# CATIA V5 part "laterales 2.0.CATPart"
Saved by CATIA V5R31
Part number: laterales 2.0
Bounding box of the stored display mesh (mm): x 0 to 3.3, y -96.6 to 96.6, z 0 to 315
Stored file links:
  C:\Users\189361\Desktop\laterales 2.0.CATPart
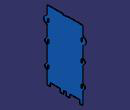
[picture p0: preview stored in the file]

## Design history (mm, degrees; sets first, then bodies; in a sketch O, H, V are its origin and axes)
Body1 (main body)
  Sketch1 on yz-plane, origin (0, 0, 0), H (0, 1, 0), V (0, 0, 1)
    point P1 (0, 15)
    line L1 (0, 15) -> (-6.45, 15)
    point P2 (-6.45, 15)
    line L2 (-6.45, 15) -> (-6.45, 0)
    point P3 (-6.45, 0)
    line L3 (-6.45, 0) -> (-21.75, 0)
    point P4 (-21.75, 0)
    line L4 (-21.75, 0) -> (-21.75, 15)
    point P5 (-21.75, 15)
    line L5 (-21.75, 15) -> (-66.45, 15)
    point P6 (-66.45, 15)
    line L6 (-66.45, 15) -> (-66.45, 0)
    point P7 (-66.45, 0)
    line L7 (-66.45, 0) -> (-81.6, 0)
    point P8 (-81.6, 0)
    construction line L8 (-14.1, -19.5641) -> (-14.1, 21.2481)
    point P9 (-14.1, -19.5641)
    point P10 (-14.1, 21.2481)
    construction line L9 (-264.7975, 72.5) -> (-53.2108, 72.5)
    point P11 (-264.7975, 72.5)
    point P12 (-53.2108, 72.5)
    point P13 (-81.6, 80.15)
    point P14 (-75, 80.15)
    point P15 (-75, 64.85)
    point P16 (-81.6, 64.85)
    line L10 (-81.6, 89.8205) -> (-81.6, 155.1795)
    construction line L11 (-287.0733, 122.5) -> (-61.3587, 122.5)
    point P18 (-61.3587, 122.5)
    point P19 (-264.7975, 172.5)
    point P20 (-53.2108, 172.5)
    point P21 (-81.6, 164.85)
    point P22 (-75, 164.85)
    point P23 (-75, 180.15)
    point P24 (-81.6, 180.15)
    construction line L12 (-264.7975, 172.5) -> (-53.2108, 172.5)
    line L13 (-81.6, 189.8205) -> (-81.6, 232.0871)
    point P25 (-81.6, 262.65)
    line L14 (-81.6, 277.9129) -> (-81.6, 315)
    point P26 (-81.6, 315)
    line L15 (-81.6, 315) -> (-7.5, 315)
    point P27 (-7.5, 315)
    construction line L16 (-258.7443, 255) -> (-43.5524, 255)
    point P29 (-43.5524, 255)
    arc A1 centre (-81.6, 72.5) radius 10 from (-86.6, 81.1603) to (-86.6, 63.8397) ccw
    point P30 (-81.6, 72.5)
    point P31 (-80.687, 62.5418)
    point P32 (-81.6, 92.4667)
    point P33 (-81.6, 172.5)
    arc A2 centre (-81.6, 172.5) radius 10 from (-86.6, 163.8397) to (-86.6, 181.1603) cw
    arc A3 centre (-81.6, 255) radius 15 from (-87.6, 268.7477) to (-87.6, 241.2523) ccw
    point P34 (-81.6, 255)
    arc A4 centre (-91.6, 55.1795) radius 10 from (-86.6, 63.8397) to (-81.6, 55.1795) cw
    point P35 (-86.6, 63.8397)
    point P36 (-81.6, 55.1795)
    point P38 (-81.6, 89.8205)
    point P39 (-86.6, 81.1603)
    arc A5 centre (-91.6, 89.8205) radius 10 from (-86.6, 81.1603) to (-81.6, 89.8205) ccw
    point P41 (-81.6, 189.8205)
    point P42 (-86.6, 181.1603)
    arc A6 centre (-91.6, 189.8205) radius 10 from (-86.6, 181.1603) to (-81.6, 189.8205) ccw
    point P44 (-81.6, 155.1795)
    point P45 (-86.6, 163.8397)
    arc A7 centre (-91.6, 155.1795) radius 10 from (-86.6, 163.8397) to (-81.6, 155.1795) cw
    arc A8 centre (-91.6, 232.0871) radius 10 from (-87.6, 241.2523) to (-81.6, 232.0871) cw
    point P47 (-87.6, 241.2523)
    point P48 (-81.6, 232.0871)
    point P50 (-81.6, 277.9129)
    point P51 (-87.6, 268.7477)
    arc A9 centre (-91.6, 277.9129) radius 10 from (-87.6, 268.7477) to (-81.6, 277.9129) ccw
    line L17 (-7.5, 315) -> (-7.5, 311.7)
    point P53 (-7.5, 311.7)
    line L18 (-7.5, 311.7) -> (0, 311.7)
    point P54 (0, 311.7)
    point P55 (0, 0)
    construction line L19 (0, 15) -> (-81.6, 15)
    point P56 (-81.6, 15)
    line L20 (-81.6, 0) -> (-81.6, 55.1795)
    point P57 (0, 0)
    point P58 (0, 15)
    point P59 (6.45, 15)
    point P60 (6.45, 0)
    point P61 (21.75, 0)
    point P62 (21.75, 15)
    point P63 (66.45, 15)
    point P64 (66.45, 0)
    point P65 (81.6, 0)
    point P66 (14.1, 21.2481)
    point P67 (14.1, -19.5641)
    construction line L21 (14.1, -19.5641) -> (14.1, 21.2481)
    point P68 (53.2108, 72.5)
    point P69 (61.3587, 122.5)
    point P70 (53.2108, 172.5)
    point P71 (81.6, 315)
    point P72 (7.5, 315)
    point P73 (43.5524, 255)
    point P74 (80.687, 62.5418)
    point P75 (81.6, 92.4667)
    point P76 (86.6, 63.8397)
    point P77 (81.6, 55.1795)
    point P79 (81.6, 89.8205)
    point P80 (86.6, 81.1603)
    point P82 (81.6, 189.8205)
    point P83 (86.6, 181.1603)
    point P85 (81.6, 155.1795)
    point P86 (86.6, 163.8397)
    point P88 (87.6, 241.2523)
    point P89 (81.6, 232.0871)
    point P91 (81.6, 277.9129)
    point P92 (87.6, 268.7477)
    point P94 (7.5, 311.7)
    point P95 (0, 311.7)
    point P96 (0, 0)
    point P97 (81.6, 15)
    construction line L22 (0, 15) -> (81.6, 15)
    line L23 (0, 15) -> (6.45, 15)
    line L24 (6.45, 15) -> (6.45, 0)
    line L25 (6.45, 0) -> (21.75, 0)
    line L26 (21.75, 0) -> (21.75, 15)
    line L27 (21.75, 15) -> (66.45, 15)
    line L28 (66.45, 15) -> (66.45, 0)
    line L29 (66.45, 0) -> (81.6, 0)
    line L30 (81.6, 89.8205) -> (81.6, 155.1795)
    line L31 (81.6, 189.8205) -> (81.6, 232.0871)
    line L32 (81.6, 277.9129) -> (81.6, 315)
    line L33 (81.6, 315) -> (7.5, 315)
    arc A10 centre (81.6, 72.5) radius 10 from (86.6, 81.1603) to (86.6, 63.8397) cw
    arc A11 centre (81.6, 172.5) radius 10 from (86.6, 163.8397) to (86.6, 181.1603) ccw
    arc A12 centre (81.6, 255) radius 15 from (87.6, 268.7477) to (87.6, 241.2523) cw
    arc A13 centre (91.6, 55.1795) radius 10 from (86.6, 63.8397) to (81.6, 55.1795) ccw
    arc A14 centre (91.6, 89.8205) radius 10 from (86.6, 81.1603) to (81.6, 89.8205) cw
    arc A15 centre (91.6, 189.8205) radius 10 from (86.6, 181.1603) to (81.6, 189.8205) cw
    arc A16 centre (91.6, 155.1795) radius 10 from (86.6, 163.8397) to (81.6, 155.1795) ccw
    arc A17 centre (91.6, 232.0871) radius 10 from (87.6, 241.2523) to (81.6, 232.0871) ccw
    arc A18 centre (91.6, 277.9129) radius 10 from (87.6, 268.7477) to (81.6, 277.9129) cw
    line L34 (7.5, 315) -> (7.5, 311.7)
    line L35 (7.5, 311.7) -> (0, 311.7)
    line L36 (81.6, 0) -> (81.6, 55.1795)
    axis line L37 (-81.6, 72.5) -> (-75, 72.5)
    point P98 (-75, 72.5)
    point P99 (-78.3, 80.15)
    line L38 (-78.3, 80.15) -> (-75, 80.15)
    line L39 (-75, 80.15) -> (-75, 64.85)
    line L40 (-75, 64.85) -> (-78.3, 64.85)
    line L41 (-78.3, 64.85) -> (-78.3, 80.15)
    point P100 (-75, 80.15)
    point P101 (-75, 64.85)
    point P102 (-78.3, 64.85)
    point P103 (-75, 164.85)
    point P104 (-75, 180.15)
    point P105 (-75, 172.5)
    point P106 (-78.3, 164.85)
    point P107 (-75, 164.85)
    point P108 (-75, 180.15)
    point P109 (-78.3, 180.15)
    line L42 (-78.3, 164.85) -> (-75, 164.85)
    line L43 (-75, 164.85) -> (-75, 180.15)
    line L44 (-75, 180.15) -> (-78.3, 180.15)
    line L45 (-78.3, 180.15) -> (-78.3, 164.85)
    point P110 (-78.3, 262.65)
    line L46 (-78.3, 262.65) -> (-75, 262.65)
    line L47 (-75, 262.65) -> (-75, 247.35)
    line L48 (-75, 247.35) -> (-78.3, 247.35)
    line L49 (-78.3, 247.35) -> (-78.3, 262.65)
    point P111 (-75, 262.65)
    point P112 (-75, 247.35)
    point P113 (-78.3, 247.35)
    point P114 (78.3, 262.65)
    point P115 (75, 262.65)
    point P116 (75, 247.35)
    point P117 (78.3, 247.35)
    line L50 (78.3, 262.65) -> (75, 262.65)
    line L51 (75, 262.65) -> (75, 247.35)
    line L52 (75, 247.35) -> (78.3, 247.35)
    line L53 (78.3, 247.35) -> (78.3, 262.65)
    point P118 (75, 164.85)
    point P119 (75, 180.15)
    point P120 (75, 164.85)
    point P121 (75, 180.15)
    point P122 (75, 172.5)
    point P123 (78.3, 164.85)
    point P124 (75, 164.85)
    point P125 (75, 180.15)
    point P126 (78.3, 180.15)
    line L54 (78.3, 164.85) -> (75, 164.85)
    line L55 (75, 164.85) -> (75, 180.15)
    line L56 (75, 180.15) -> (78.3, 180.15)
    line L57 (78.3, 180.15) -> (78.3, 164.85)
    point P127 (75, 80.15)
    point P128 (75, 64.85)
    point P129 (75, 72.5)
    point P130 (78.3, 80.15)
    point P131 (75, 80.15)
    point P132 (75, 64.85)
    point P133 (78.3, 64.85)
    line L58 (78.3, 80.15) -> (75, 80.15)
    line L59 (75, 80.15) -> (75, 64.85)
    line L60 (75, 64.85) -> (78.3, 64.85)
    line L61 (78.3, 64.85) -> (78.3, 80.15)
    length L3 = 15.3
    distance L8 L2 = 7.65
    distance L8 V = 14.1
    length L6 = 15
    length L7 = 15.15
    distance L9 L5 = 57.5
    distance L11 L9 = 50
    distance L16 L15 = 60
    distance L15 L5 = 300
    radius A1 = 10
    radius A3 = 15
    radius A4 = 10
    radius A8 = 10
    length L18 = 7.5
    length L17 = 3.3
    length L19 = 81.6
    length L37 = 6.6
    length L38 = 3.3
    length L39 = 15.3
    distance L9 L38 = 7.65
    length L46 = 3.3
    length L47 = 15.3
    distance L46 L16 = 7.65
    coincidence: P1 V, P3 H, P5 L1, P7 H, P25 L10, P30 L9, L10 P32, P34 L10, P34 L16, L14 L13, A1 P31, P54 V, L10 P56, P33 L13, P98 L39, L47 L43
    horizontal: L1 H, L3 H, L7 H, L5 H, L9 H, L11 H, L15 H, L16 H, L18 H, L19 H, L37 H, L38 H, L40 H, L46 H, L48 H
    vertical: L2 V, L4 V, L6 V, L8 V, L10 V, L13 V, L14 V, L17 V, L20 V, L39 V, L41 V, L47 V, L49 V
    equal size: L2 L4, L4 L6
    symmetry: P11 P19 L11, P12 P20 L11, P13 P21 L11, P14 P22 L11, P15 P23 L11, P16 P24 L11, L9 L12 L11, A1 A2 L11, P36 P38 L9, P35 P39 L9, A4 A5 L9, P36 P41 L11, P35 P42 L11, A4 A6 L11, P38 P44 L11, P39 P45 L11, A5 A7 L11, P48 P50 L16, P47 P51 L16, A8 A9 L16, O P55 V, O P57 V, P1 P58 V, P2 P59 V, P3 P60 V, P4 P61 V, P5 P62 V, P6 P63 V, P7 P64 V, P8 P65 V, P10 P66 V, P9 P67 V, L8 L21 V, P12 P68 V, P18 P69 V, P20 P70 V, P26 P71 V, P27 P72 V, P29 P73 V, P31 P74 V, P32 P75 V, P35 P76 V, P36 P77 V, P38 P79 V, P39 P80 V, P41 P82 V, P42 P83 V, P44 P85 V, P45 P86 V, P47 P88 V, P48 P89 V, P50 P91 V, P51 P92 V, P53 P94 V, P54 P95 V, P55 P96 V, P56 P97 V, L19 L22 V, L1 L23 V, L2 L24 V, L3 L25 V, L4 L26 V, L5 L27 V, L6 L28 V, L7 L29 V, L10 L30 V, L13 L31 V, L14 L32 V, L15 L33 V, A1 A10 V, A2 A11 V, A3 A12 V, A4 A13 V, A5 A14 V, A6 A15 V, A7 A16 V, A8 A17 V, A9 A18 V, L17 L34 V, L18 L35 V, L20 L36 V, P14 P103 L11, P15 P104 L11, P98 P105 L11, P99 P106 L11, P100 P107 L11, P101 P108 L11, P102 P109 L11, L38 L42 L11, L39 L43 L11, L40 L44 L11, L41 L45 L11, P110 P114 V, P111 P115 V, P112 P116 V, P113 P117 V, L46 L50 V, L47 L51 V, L48 L52 V, L49 L53 V, P22 P118 V, P23 P119 V, P103 P120 V, P104 P121 V, P105 P122 V, P106 P123 V, P107 P124 V, P108 P125 V, P109 P126 V, L42 L54 V, L43 L55 V, L44 L56 V, L45 L57 V, P14 P127 V, P15 P128 V, P98 P129 V, P99 P130 V, P100 P131 V, P101 P132 V, P102 P133 V, L38 L58 V, L39 L59 V, L40 L60 V, L41 L61 V
    tangency: A4 A1, A8 L13, A8 A3, L14 A8, L20 A4, A5 L10, A7 L10, A6 L13
  Pad1: profile Sketch1, direction (1, 0, 0), length 3.3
